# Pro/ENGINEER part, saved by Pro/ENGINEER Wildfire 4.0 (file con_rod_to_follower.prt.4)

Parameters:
  METRIC = "NO"

Other parameters: PITCH, DRILL_POINT_ANGLE, DRILL_DEPTH, DRILL_DIAMETER, THREAD_DIAMETER, THREADS_PER_INCH, THREAD_DEPTH, THREAD_LENGTH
